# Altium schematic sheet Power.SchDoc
size A4; Revision: C.2
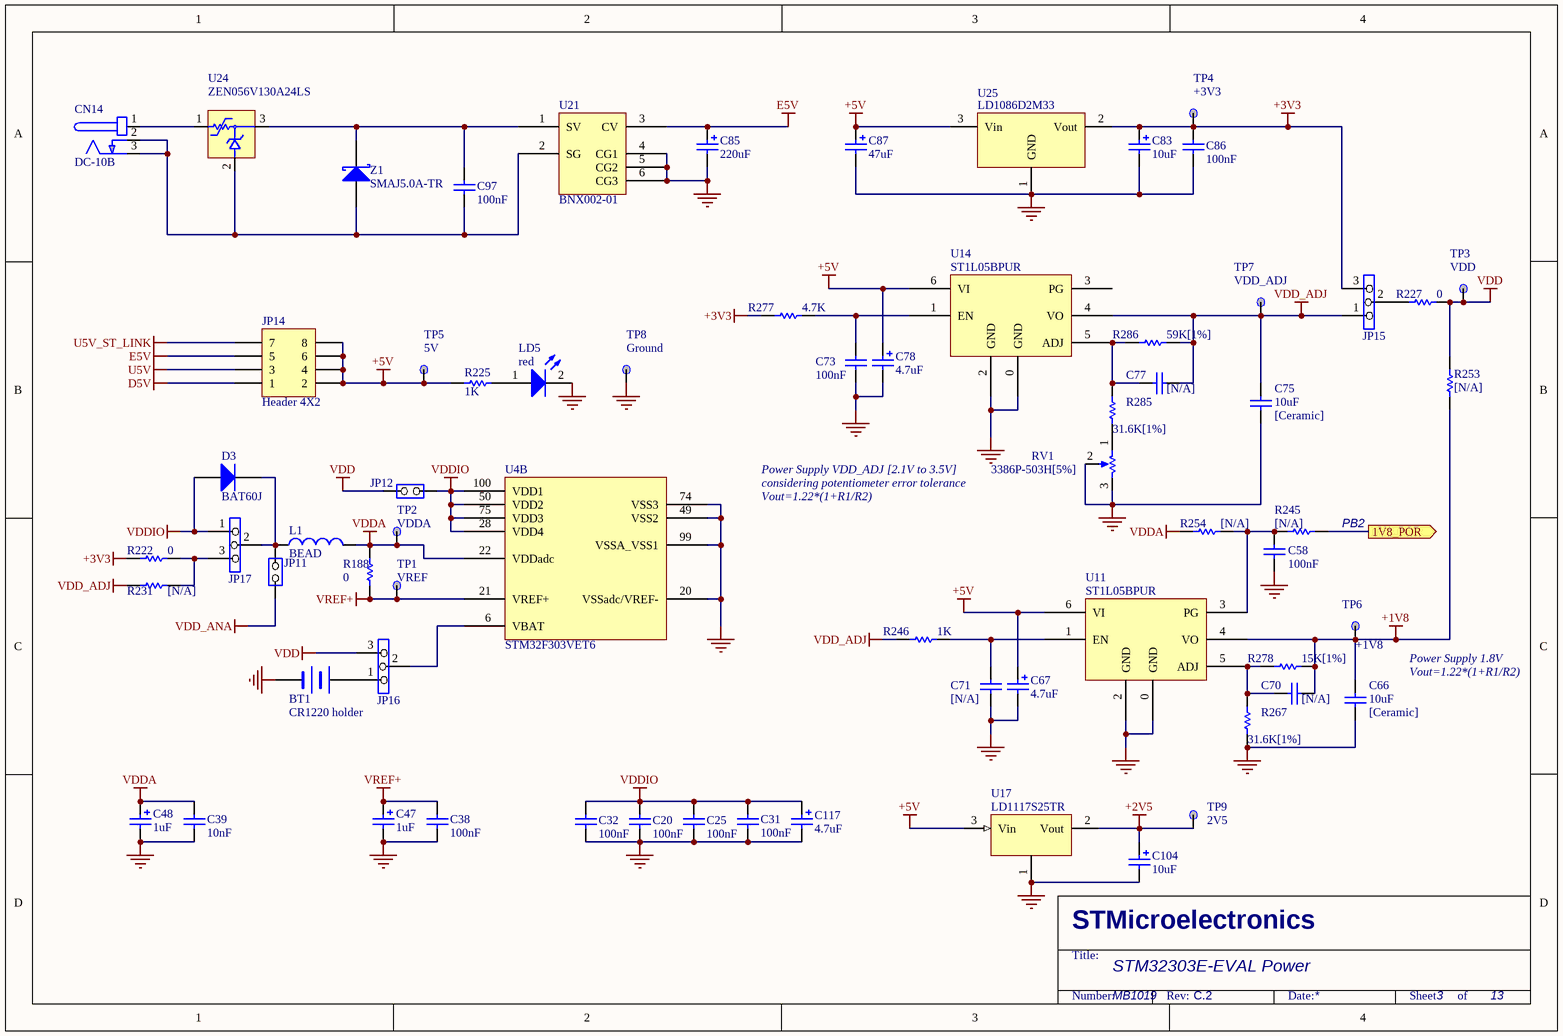
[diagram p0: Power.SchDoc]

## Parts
BT1  CR1220 holder  [LI1220_1]
C20  100nF  [0603C]
C25  100nF  [0603C]
C31  100nF  [0603C]
C32  100nF  [0603C]
C38  100nF  [0603C]
C39  10nF  [0603C]
C47  1uF  [TAN-A]
C48  1uF  [TAN-A]
C58  100nF  [0603C]
C66  10uF  [0805C]
C67  4.7uF  [TAN-A]
C70  [N/A]  [0603C]
C71  [N/A]  [0603C]
C73  100nF  [0603C]
C75  10uF  [0805C]
C77  [N/A]  [0603C]
C78  4.7uF  [TAN-A]
C83  10uF  [TAN-A]
C85  220uF  [C310M]
C86  100nF  [0603C]
C87  47uF  [C200M]
C97  100nF  [0603C]
C104  10uF  [TAN-A]
C117  4.7uF  [TAN-A]
CN14  DC-10B  [DC10B]
D3  BAT60J  [SOD-323]
JP11  (no value)  [SIP2]
JP12  (no value)  [SIP2]
JP14  Header 4X2  [2*4P]
JP15  (no value)  [SIP3]
JP16  (no value)  [SIP3]
JP17  (no value)  [SIP3]
L1  BEAD  [0603L]
LD5  red  [0603D]
R188  0  [0603R]
R222  0  [0603R]
R225  1K  [0603R]
R227  0  [0603R]
R231  [N/A]  [0603R]
R245  [N/A]  [0603R]
R246  1K  [0603R]
R253  [N/A]  [0603R]
R254  [N/A]  [0603R]
R267  31.6K[1%]  [0603R]
R277  4.7K  [0603R]
R278  15K[1%]  [0603R]
R285  31.6K[1%]  [0603R]
R286  59K[1%]  [0603R]
RV1  3386P-503H[5%]  [3296W]
TP1  VREF  [TP]
TP2  VDDA  [TP]
TP3  VDD  [TP]
TP4  +3V3  [TP]
TP5  5V  [TP]
TP6  +1V8  [TP]
TP7  VDD_ADJ  [TP]
TP8  Ground  [TP]
TP9  2V5  [TP]
U4  STM32F303VET6  [IC149-100-025-B5]  (part B of 2)
U11  ST1L05BPUR  [DFN6(3X3)]
U14  ST1L05BPUR  [DFN6(3X3)]
U17  LD1117S25TR  [SOT-223]
U21  BNX002-01  [BNX001]
U24  ZEN056V130A24LS  [polyzen]
U25  LD1086D2M33  [D2PAK/A]
Z1  SMAJ5.0A-TR  [1R1C]

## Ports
1V8_POR (out)

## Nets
+1V8: C66.1 C70.2 R253.2 R278.1 TP6.1 U11.4(VO)
+2V5: C104.1 TP9.1 U17.2(Vout)
+3V3: C83.1 C86.1 JP15.3 R222.2 R277.2 TP4.1 U25.2(Vout)
+5V: C67.1 C78.1 C87.1 JP14.2 JP14.4 JP14.6 JP14.8 R225.2 TP5.1 U11.6(VI) U14.6(VI) U17.3(Vin) U25.3(Vin)
D5V: JP14.1
E5V: C85.1 JP14.5 U21.3(CV)
GND: BT1.2(-) C20.2 C25.2 C31.1 C32.2 C38.1 C39.1 C47.2 C48.2 C58.2 C66.2 C67.2 C71.2 C73.2 C75.2 C78.2 C83.2 C85.2 C86.2 C87.2 C104.2 C117.2 LD5.2(K) R267.2 RV1.2(TAP) RV1.3(TOP) TP8.1 U4.20(VSSadc/VREF-) U4.49(VSS2) U4.74(VSS3) U4.99(VSSA_VSS1) U11.0(GND) U11.2(GND) U14.0(GND) U14.2(GND) U17.1 U21.4(CG1) U21.5(CG2) U21.6(CG3) U25.1(GND)
U5V: JP14.3
U5V_ST_LINK: JP14.7
VDD: JP12.2(NO) JP16.3 R227.1 R253.1 TP3.1
VDD_ADJ: C75.1 C77.2 JP15.1 R231.2 R246.2 R286.1 TP7.1 U14.4(VO)
VDD_ANA: JP11.1(COMMON)
VDDA: C39.2 C48.1 L1.2 R188.1 R254.1 TP2.1 U4.22(VDDadc)
VDDIO: C20.1 C25.1 C31.2 C32.1 C117.1 D3.1(A) JP12.1(COMMON) JP17.1 U4.28(VDD4) U4.50(VDD2) U4.75(VDD3) U4.100(VDD1)
VREF+: C38.2 C47.1 R188.2 TP1.1 U4.21(VREF+)
1V8_POR: R245.1 ; port 1V8_POR
NetBT1_1: BT1.1(+) JP16.1
NetC58_1: C58.1 R245.2 R254.2 U11.3(PG)
NetC70_1: C70.1 R267.1 R278.2 U11.5(ADJ)
NetC71_1: C71.1 R246.1 U11.1(EN)
NetC73_1: C73.1 R277.1 U14.1(EN)
NetC77_1: C77.1 R285.1 R286.2 U14.5(ADJ)
NetC97_1: C97.1 U21.1(SV) U24.3 Z1.2(K)
NetC97_2: C97.2 CN14.2(GND) CN14.3(GND) U21.2(SG) U24.2 Z1.1(A)
NetCN14_1: CN14.1(+) U24.1
NetD3_2: D3.2(K) JP11.2(NO) JP17.2 L1.1
NetJP15_2: JP15.2 R227.2
NetJP16_2: JP16.2 U4.6(VBAT)
NetJP17_3: JP17.3 R222.1 R231.1
NetLD5_1: LD5.1(A) R225.1
NetR285_2: R285.2 RV1.1(BOT)

Not connected (* = marked no-connect by the designer): U14 3(PG)

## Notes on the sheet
- (near C75) [Ceramic]
- Power Supply VDD_ADJ [2.1V to 3.5V]
- Vout=1.22*(1+R1/R2)
- considering potentiometer error tolerance
- (near R245) PB2
- (near C66) [Ceramic]
- Power Supply 1.8V
- STM32303E-EVAL Power
- MB1019
- 3
- 13

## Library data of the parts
BT1 = BATTERY
C20 C25 C32 = CAP: Capacitor
C31 C38 C58 C66 C70 C71 C73 C75 C77 C86 = Cap: Capacitor; Value: 10nF
C39 = Cap: Capacitor
C47 C48 C87 = Cap Pol1: Polarized Capacitor (Radial); Value: 10uF
C67 C78 C117 = Cap Pol1: Polarized Capacitor (Radial); Value: 100pF
C83 C104 = Cap Pol1: Polarized Capacitor (Radial)
C85 = Cap Pol1: Polarized Capacitor (Radial); Value: 47uF
C97 = CAP: Capacitor; Value: 100pF
CN14 = PJ202A
D3 = Diode: Default Diode; Code - JEDEC: DO-214-AB
JP11 JP12 = JP2
JP14 = Header 4X2: Header, 4-Pin, Dual row
JP15-JP17 = Jumper3
L1 = Inductor: Value: 100uH
LD5 = LED2: Typical RED, GREEN, YELLOW, AMBER GaAs LED
R188 R222 R227 R231 R245 R253 R267 R278 R285 R286 = Res1: Resistor; Value: 1K
R225 R246 = res1: Resistor
R254 R277 = res1: Resistor; Value: 1K
RV1 = RV
TP1-TP9 = TP
U4 = STM32F303VCT6
U11 U14 = ST1L05
U17 = LD1117
U21 = BNX002
U25 = VOLTREG1
Z1 = D Schottky: Schottky Diode; Code - JEDEC: DO-214-AA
